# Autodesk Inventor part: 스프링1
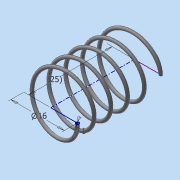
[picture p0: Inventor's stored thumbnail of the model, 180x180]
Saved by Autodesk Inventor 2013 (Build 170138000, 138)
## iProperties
Created: 2015-11
Part Number: 스프링1
Material: 강철, 탄소
Document SubType Name: Modeling
Designer: dgall
Density: 7.87 g/cm^3
Mass: 1.54771 g
Surface Area: 7.8879 cm^2
Volume: 0.19666 cm^3
Author: dgall
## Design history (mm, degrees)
sketch "스케치1"
  geometry: L1 (8, 0)-(0, 0); L2 (0, 0)-(0, 16.67); L3 (0, 16.67)-(8, 16.67); C1 r 0.5 at (8, 0)
  constraints: 6 end point, 1 centre point, 1 coincident, 1 horizontal, 1 parallel, 1 perpendicular, 1 vertical alignment
  dimensions: "d5" = 16 diameter of L1.start L2; "d7" = 16.66987 distance of L1.end L2.end (derived); "d8" = 1 diameter of C1
feature "코일1" pitch "d9" = 10; turns "d11" = 5; dims "d10" = 16.66987 (= d7), "d12" = 0, angle "d13" = 90 deg, angle "d14" = 90 deg, "d15" = 0, "d16" = 0
sketch "스케치2"
  geometry: L1 (-10, 0)-(10, 0); L2 (10, 0)-(10, -5); L3 (10, -5)-(-10, -5); L4 (-10, -5)-(-10, 0); L5 (-10, 30)-(10, 30); L6 (10, 30)-(10, 25); L7 (10, 25)-(-10, 25); L8 (-10, 25)-(-10, 30); 4 further points
  constraints: 16 end point, 4 parallel, 3 midpoint, 2 horizontal, 2 perpendicular, 1 coincident, 1 vertical alignment
  dimensions: "d17" = 25 distance between parallel lines of L7 L1; "d18" = 5 distance of L7.end L5.start; "d19" = 5 distance of L3.end L1.start; "d20" = 20 distance of L2.end L3.end; "d21" = 20 distance of L5.start L5.end
extrude "돌출1" cut sketch "스케치2" stored distance "d22" = 30; taper "d23" = 0 deg
node "솔리드1"
